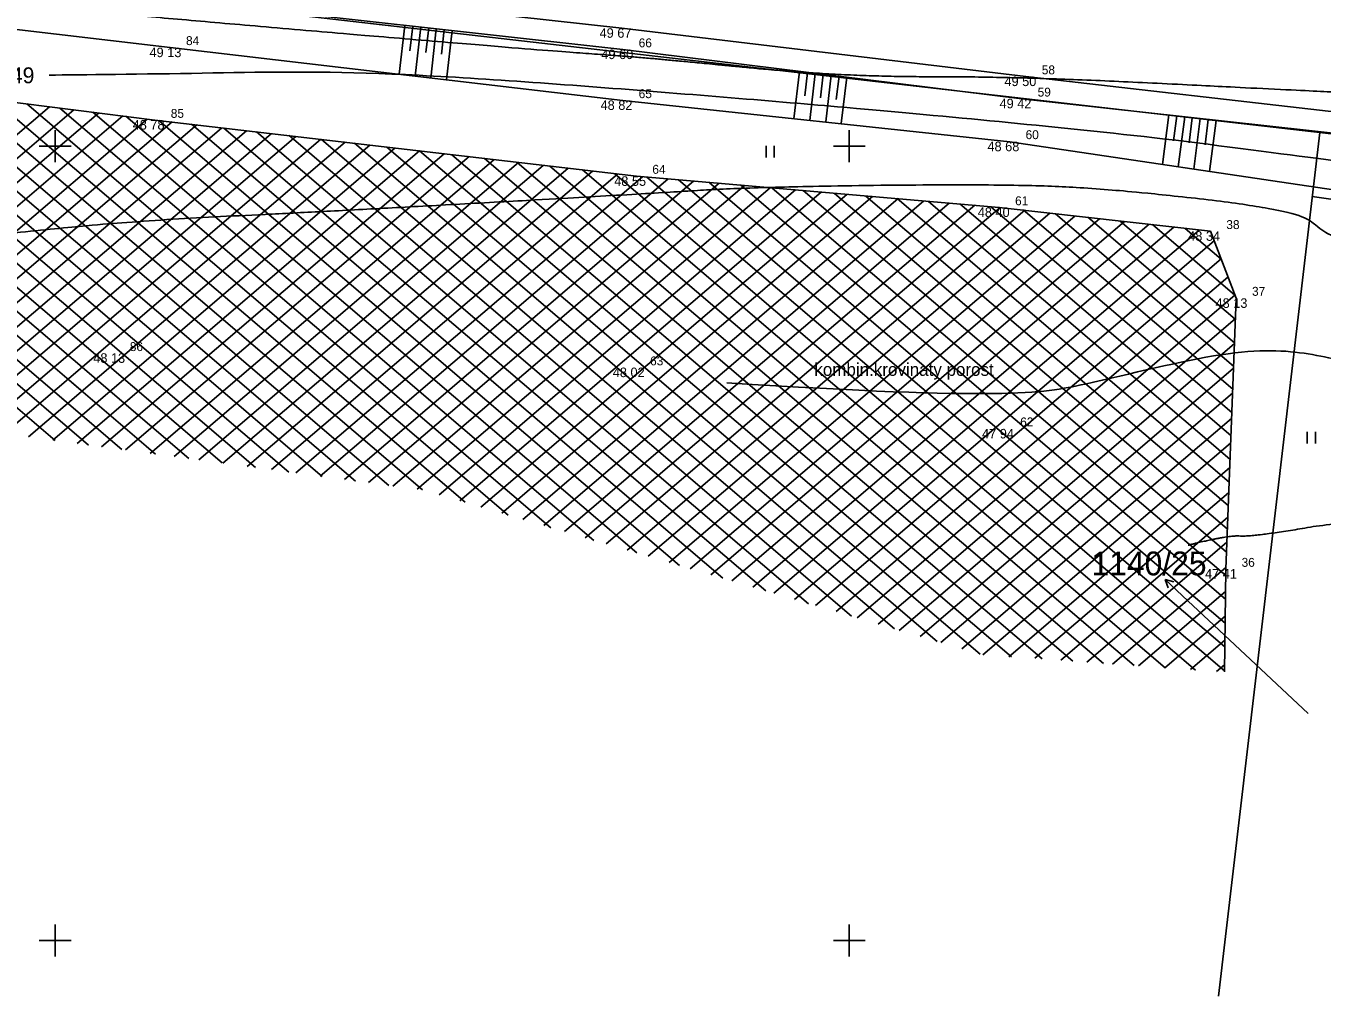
# Model space of a CAD drawing. Extents: x -704057 to -703795, y -1008732 to -1008584.
# Drawn here: x -703875.92 to -703835.12, y -1008701.75 to -1008671.22 of the extents above; entities that cross this region are included whole.
import ezdxf

# ---------------------------------------------------------------- set-up
doc = ezdxf.new("R2010")
doc.units = 0
for name, color, linetype in [('Z_body', 7, 'Continuous'), ('Z_body_cisla', 7, 'Continuous'), ('Z_body_vysky', 7, 'Continuous'), ('Z_hekt_sit', 7, 'Continuous'), ('Z_katastr_cisla_pozemkove', 7, 'Continuous'), ('Z_katastr_hranice', 7, 'Continuous'), ('Z_komunikace_zpevn_pl', 7, 'Continuous'), ('Z_popis', 7, 'Continuous'), ('Z_teren_hrany_paty', 7, 'Continuous'), ('Z_vrstevnice_popis', 7, 'Continuous'), ('Z_vrstevnice_vedlejsi', 7, 'Continuous'), ('Z_zelen_souvisla', 7, 'Continuous')]:
    doc.layers.add(name, color=color, linetype=linetype)

# ---------------------------------------------------------------- blocks, each defined once
blk = doc.blocks.new('POINT_DISPLAY')
blk.add_line((0, 0), (0, 0))
blk = doc.blocks.new('Z61')
for p, q in [((0, 0.75), (-0.13, 0.5)), ((0, 0), (0, 0.75)), ((0, 0.75), (0.13, 0.5))]:
    blk.add_line(p, q)
blk = doc.blocks.new('Z306')
for p, q in [((-0.13, 0.17), (-0.13, -0.2)), ((0.13, 0.17), (0.13, -0.2))]:
    blk.add_line(p, q)

msp = doc.modelspace()

# ---------------------------------------------------------------- linework, layer by layer
at = {"layer": 'Z_hekt_sit'}
for p, q in [((-703875, -1008674.5), (-703875, -1008675.5)), ((-703850, -1008674.5), (-703850, -1008675.5)), ((-703875.5, -1008675), (-703874.5, -1008675)), ((-703850.5, -1008675), (-703849.5, -1008675)), ((-703875, -1008699.5), (-703875, -1008700.5)), ((-703850, -1008699.5), (-703850, -1008700.5)), ((-703875.5, -1008700), (-703874.5, -1008700)), ((-703850.5, -1008700), (-703849.5, -1008700))]:
    msp.add_line(p, q, dxfattribs=at)
at = {"layer": 'Z_katastr_cisla_pozemkove'}
msp.add_lwpolyline([(-703835.55, -1008692.86), (-703839.51, -1008689.15)], dxfattribs=at)
at = {"layer": 'Z_katastr_hranice'}
for p, q in [((-703871.83, -1008670.35), (-703828.51, -1008675.34)), ((-703835.19, -1008674.57), (-703838.38, -1008701.75)), ((-703800.45, -1008681.63), (-703835.43, -1008676.59))]:
    msp.add_line(p, q, dxfattribs=at)
at = {"layer": 'Z_komunikace_zpevn_pl'}
for p, q in [((-703870.95, -1008669.76), (-703857.16, -1008671.29)), ((-703857.16, -1008671.29), (-703844.44, -1008672.81)), ((-703844.44, -1008672.81), (-703833.37, -1008674.08))]:
    msp.add_line(p, q, dxfattribs=at)
at = {"layer": 'Z_teren_hrany_paty'}
for p, q in [((-703883.41, -1008670.49), (-703871.38, -1008671.9)), ((-703857.13, -1008671.96), (-703871.14, -1008670.4)), ((-703863.99, -1008671.2), (-703864.17, -1008672.74)), ((-703863.74, -1008671.22), (-703863.83, -1008672)), ((-703863.49, -1008671.25), (-703863.67, -1008672.8)), ((-703863.24, -1008671.28), (-703863.33, -1008672.05)), ((-703863, -1008671.31), (-703863.17, -1008672.86)), ((-703862.75, -1008671.33), (-703862.84, -1008672.11)), ((-703862.5, -1008671.36), (-703862.68, -1008672.91)), ((-703871.38, -1008671.9), (-703857.13, -1008673.56)), ((-703844.57, -1008673.51), (-703857.13, -1008671.96)), ((-703851.57, -1008672.65), (-703851.74, -1008674.14)), ((-703851.32, -1008672.68), (-703851.4, -1008673.42)), ((-703851.07, -1008672.71), (-703851.24, -1008674.19)), ((-703850.82, -1008672.74), (-703850.91, -1008673.48)), ((-703850.57, -1008672.77), (-703850.74, -1008674.24)), ((-703850.32, -1008672.8), (-703850.41, -1008673.53)), ((-703850.08, -1008672.83), (-703850.25, -1008674.29)), ((-703857.13, -1008673.56), (-703844.95, -1008674.86)), ((-703834.19, -1008674.66), (-703844.57, -1008673.51)), ((-703839.94, -1008674.02), (-703840.14, -1008675.58)), ((-703839.69, -1008674.05), (-703839.79, -1008674.83)), ((-703839.44, -1008674.08), (-703839.65, -1008675.65)), ((-703839.2, -1008674.11), (-703839.3, -1008674.9)), ((-703838.95, -1008674.13), (-703839.15, -1008675.72)), ((-703838.7, -1008674.16), (-703838.8, -1008674.96)), ((-703838.45, -1008674.19), (-703838.66, -1008675.8)), ((-703844.95, -1008674.86), (-703833.82, -1008676.52))]:
    msp.add_line(p, q, dxfattribs=at)
at = {"layer": 'Z_vrstevnice_popis'}
for points in [[(-703875.185, -1008672.765), (-703874.223, -1008672.756), (-703870.137, -1008672.712), (-703865.404, -1008672.596), (-703857.13, -1008673.191), (-703849.187, -1008673.851), (-703844.786, -1008674.276), (-703839.886, -1008674.766), (-703834.01, -1008675.565), (-703833.183, -1008675.626), (-703829.469, -1008675.762), (-703820.395, -1008676.551), (-703819.724, -1008676.752), (-703817.382, -1008677.089), (-703816.139, -1008677.242), (-703815.655, -1008677.56), (-703814.182, -1008677.821), (-703814.089, -1008677.838)], [(-703853.857, -1008682.453), (-703845.141, -1008682.991), (-703842.815, -1008682.602), (-703837.88, -1008681.328), (-703835.453, -1008681.475), (-703833.605, -1008682.013), (-703832.889, -1008681.487), (-703832.436, -1008681.417), (-703832.363, -1008681.41)]]:
    msp.add_open_spline(points, degree=3, dxfattribs=at)
at = {"layer": 'Z_vrstevnice_vedlejsi'}
for points in [[(-703806.645, -1008669.413), (-703810.064, -1008669.091), (-703818.896, -1008668.231), (-703821.949, -1008667.886), (-703832.348, -1008666.911), (-703832.429, -1008666.905), (-703837.82, -1008666.255), (-703832.713, -1008666.908), (-703832.355, -1008666.952), (-703825.705, -1008667.99), (-703819.056, -1008669.026), (-703815.993, -1008669.415), (-703810.462, -1008670.24), (-703806.87, -1008671.09), (-703808.766, -1008673.591), (-703809.75, -1008673.886), (-703817.454, -1008673.52), (-703819.628, -1008673.248), (-703826.836, -1008673.24), (-703833.27, -1008673.353), (-703835.286, -1008673.278), (-703844.44, -1008672.81), (-703850.152, -1008672.821), (-703855.806, -1008672.275), (-703857.13, -1008672.165), (-703860.162, -1008671.947), (-703871.237, -1008671.005), (-703876.973, -1008670.473), (-703883.276, -1008669.953), (-703888.652, -1008669.207), (-703892.007, -1008668.787), (-703895.701, -1008668.459), (-703900.931, -1008667.965), (-703907.22, -1008668.487), (-703913.351, -1008668.979), (-703918.495, -1008669.549), (-703927.701, -1008668.863), (-703930.6, -1008669.724), (-703932.124, -1008670.909), (-703936.972, -1008673.376)], [(-703896.98, -1008678.651), (-703896.133, -1008678.493), (-703895.427, -1008678.464), (-703883.839, -1008678.545), (-703877.35, -1008677.837), (-703872.416, -1008677.342), (-703866.301, -1008677.05), (-703856.707, -1008676.518), (-703852.893, -1008676.277), (-703845.162, -1008676.191), (-703841.604, -1008676.353), (-703835.881, -1008677.017), (-703835.026, -1008677.731), (-703834.61, -1008677.894), (-703834.308, -1008677.982), (-703834.186, -1008677.892), (-703833.394, -1008677.301), (-703832.871, -1008677.385), (-703832.441, -1008677.368), (-703830.672, -1008676.925), (-703824.679, -1008677.145), (-703820.88, -1008677.475), (-703818.446, -1008678.206), (-703817.605, -1008678.327), (-703817.159, -1008678.382), (-703815.634, -1008679.383), (-703815.241, -1008679.772), (-703814.913, -1008679.988), (-703810.519, -1008681.242), (-703809.363, -1008681.548)], [(-703839.334, -1008687.561), (-703838.109, -1008687.245), (-703837.269, -1008687.296), (-703833.651, -1008686.681), (-703827.63, -1008686.764)]]:
    msp.add_open_spline(points, degree=2, dxfattribs=at)
at = {"layer": 'Z_zelen_souvisla'}
for p, q in [((-703889.57, -1008671.82), (-703875, -1008684.26)), ((-703888.5, -1008671.98), (-703873.95, -1008684.41)), ((-703887.43, -1008672.13), (-703872.9, -1008684.55)), ((-703886.36, -1008672.29), (-703871.84, -1008684.69)), ((-703885.3, -1008672.44), (-703870.79, -1008684.83)), ((-703884.23, -1008672.6), (-703869.74, -1008684.97)), ((-703883.16, -1008672.76), (-703868.69, -1008685.11)), ((-703871.86, -1008674.18), (-703883.14, -1008672.76)), ((-703882.12, -1008672.89), (-703867.64, -1008685.26)), ((-703881.08, -1008673.02), (-703866.59, -1008685.4)), ((-703880.04, -1008673.15), (-703865.54, -1008685.54)), ((-703879, -1008673.28), (-703864.49, -1008685.68)), ((-703877.97, -1008673.41), (-703863.44, -1008685.82)), ((-703885.78, -1008682.81), (-703875.18, -1008673.76)), ((-703885.01, -1008682.92), (-703874.41, -1008673.86)), ((-703876.93, -1008673.54), (-703862.09, -1008686.21)), ((-703875.89, -1008673.67), (-703860.74, -1008686.61)), ((-703874.85, -1008673.8), (-703859.39, -1008687.01)), ((-703884.25, -1008683.02), (-703873.64, -1008673.96)), ((-703883.48, -1008683.12), (-703872.87, -1008674.05)), ((-703882.72, -1008683.22), (-703872.1, -1008674.15)), ((-703881.95, -1008683.33), (-703871.32, -1008674.24)), ((-703873.81, -1008673.93), (-703858.04, -1008687.41)), ((-703872.77, -1008674.06), (-703856.69, -1008687.8)), ((-703856.7, -1008675.95), (-703871.86, -1008674.18)), ((-703871.74, -1008674.19), (-703855.34, -1008688.2)), ((-703881.19, -1008683.43), (-703870.54, -1008674.33)), ((-703880.43, -1008683.53), (-703869.76, -1008674.43)), ((-703879.66, -1008683.64), (-703868.98, -1008674.52)), ((-703878.9, -1008683.74), (-703868.2, -1008674.61)), ((-703870.71, -1008674.31), (-703853.98, -1008688.6)), ((-703869.69, -1008674.43), (-703852.63, -1008689)), ((-703868.66, -1008674.55), (-703851.28, -1008689.4)), ((-703867.63, -1008674.67), (-703849.93, -1008689.79)), ((-703878.13, -1008683.84), (-703867.42, -1008674.7)), ((-703877.37, -1008683.95), (-703866.65, -1008674.79)), ((-703876.6, -1008684.05), (-703865.87, -1008674.88)), ((-703875.84, -1008684.15), (-703865.09, -1008674.97)), ((-703875.07, -1008684.25), (-703864.31, -1008675.06)), ((-703866.61, -1008674.79), (-703848.58, -1008690.19)), ((-703865.58, -1008674.91), (-703847.23, -1008690.59)), ((-703864.56, -1008675.03), (-703845.88, -1008690.99)), ((-703874.31, -1008684.36), (-703863.53, -1008675.15)), ((-703873.54, -1008684.46), (-703862.75, -1008675.24)), ((-703872.78, -1008684.56), (-703861.97, -1008675.33)), ((-703872.01, -1008684.67), (-703861.19, -1008675.43)), ((-703863.53, -1008675.15), (-703844.89, -1008691.07)), ((-703862.51, -1008675.27), (-703843.93, -1008691.14)), ((-703861.48, -1008675.39), (-703842.96, -1008691.21)), ((-703860.46, -1008675.51), (-703842, -1008691.28)), ((-703871.25, -1008684.77), (-703860.41, -1008675.52)), ((-703870.48, -1008684.87), (-703859.64, -1008675.61)), ((-703869.72, -1008684.98), (-703858.86, -1008675.7)), ((-703868.95, -1008685.08), (-703858.08, -1008675.79)), ((-703868.19, -1008685.18), (-703857.3, -1008675.88)), ((-703859.43, -1008675.63), (-703841.03, -1008691.35)), ((-703858.4, -1008675.75), (-703840.06, -1008691.42)), ((-703857.38, -1008675.87), (-703839.1, -1008691.49)), ((-703867.42, -1008685.28), (-703856.51, -1008675.97)), ((-703866.66, -1008685.39), (-703855.71, -1008676.04)), ((-703865.89, -1008685.49), (-703854.9, -1008676.1)), ((-703865.13, -1008685.59), (-703854.1, -1008676.17)), ((-703864.37, -1008685.7), (-703853.3, -1008676.24)), ((-703863.6, -1008685.8), (-703852.49, -1008676.31)), ((-703845.28, -1008676.93), (-703856.7, -1008675.95)), ((-703856.37, -1008675.98), (-703838.19, -1008691.51)), ((-703855.38, -1008676.06), (-703838.18, -1008690.76)), ((-703854.4, -1008676.15), (-703838.17, -1008690.01)), ((-703853.41, -1008676.23), (-703838.16, -1008689.26)), ((-703852.43, -1008676.32), (-703838.15, -1008688.51)), ((-703862.91, -1008685.97), (-703851.69, -1008676.38)), ((-703862.26, -1008686.16), (-703850.88, -1008676.45)), ((-703861.6, -1008686.36), (-703850.08, -1008676.52)), ((-703860.94, -1008686.55), (-703849.27, -1008676.59)), ((-703860.28, -1008686.75), (-703848.47, -1008676.66)), ((-703859.62, -1008686.94), (-703847.66, -1008676.73)), ((-703851.45, -1008676.4), (-703838.13, -1008687.77)), ((-703850.46, -1008676.49), (-703838.1, -1008687.04)), ((-703849.48, -1008676.57), (-703838.07, -1008686.31)), ((-703848.49, -1008676.65), (-703838.04, -1008685.58)), ((-703858.96, -1008687.13), (-703846.86, -1008676.79)), ((-703858.31, -1008687.33), (-703846.05, -1008676.86)), ((-703857.65, -1008687.52), (-703845.25, -1008676.93)), ((-703856.99, -1008687.72), (-703844.47, -1008677.02)), ((-703856.33, -1008687.91), (-703843.69, -1008677.11)), ((-703847.51, -1008676.74), (-703838.02, -1008684.85)), ((-703846.52, -1008676.82), (-703837.99, -1008684.11)), ((-703845.54, -1008676.91), (-703837.96, -1008683.38)), ((-703838.63, -1008677.68), (-703845.28, -1008676.93)), ((-703844.53, -1008677.01), (-703837.93, -1008682.65)), ((-703843.51, -1008677.13), (-703837.9, -1008681.92)), ((-703855.67, -1008688.1), (-703842.9, -1008677.2)), ((-703855.01, -1008688.3), (-703842.12, -1008677.29)), ((-703854.36, -1008688.49), (-703841.34, -1008677.37)), ((-703853.7, -1008688.68), (-703840.56, -1008677.46)), ((-703853.04, -1008688.88), (-703839.78, -1008677.55)), ((-703842.49, -1008677.24), (-703837.87, -1008681.19)), ((-703841.47, -1008677.36), (-703837.85, -1008680.45)), ((-703840.45, -1008677.47), (-703837.86, -1008679.69)), ((-703852.38, -1008689.07), (-703838.99, -1008677.64)), ((-703839.43, -1008677.59), (-703838.29, -1008678.56)), ((-703837.82, -1008679.79), (-703838.63, -1008677.68)), ((-703851.72, -1008689.27), (-703838.51, -1008677.98)), ((-703851.06, -1008689.46), (-703838.29, -1008678.55)), ((-703850.41, -1008689.65), (-703838.08, -1008679.12)), ((-703849.75, -1008689.85), (-703837.86, -1008679.69)), ((-703838.15, -1008688.31), (-703837.82, -1008679.79)), ((-703849.09, -1008690.04), (-703837.85, -1008680.44)), ((-703848.43, -1008690.24), (-703837.88, -1008681.22)), ((-703847.77, -1008690.43), (-703837.91, -1008682)), ((-703847.12, -1008690.62), (-703837.94, -1008682.78)), ((-703846.46, -1008690.82), (-703837.97, -1008683.57)), ((-703845.79, -1008691.01), (-703838, -1008684.35)), ((-703844.98, -1008691.07), (-703838.03, -1008685.13)), ((-703844.16, -1008691.12), (-703838.06, -1008685.91)), ((-703843.34, -1008691.18), (-703838.09, -1008686.69)), ((-703842.52, -1008691.24), (-703838.12, -1008687.48)), ((-703841.71, -1008691.3), (-703838.15, -1008688.26)), ((-703838.19, -1008691.55), (-703838.15, -1008688.31)), ((-703840.89, -1008691.36), (-703838.16, -1008689.02)), ((-703840.07, -1008691.42), (-703838.17, -1008689.79)), ((-703839.26, -1008691.47), (-703838.18, -1008690.55)), ((-703838.44, -1008691.53), (-703838.19, -1008691.32))]:
    msp.add_line(p, q, dxfattribs=at)

# ---------------------------------------------------------------- block references
at = {"layer": 'Z_body'}
for p in [(-703857.16, -1008671.29), (-703871.38, -1008671.9), (-703857.13, -1008671.96), (-703844.44, -1008672.81), (-703857.13, -1008673.56), (-703844.57, -1008673.51), (-703871.86, -1008674.18), (-703844.95, -1008674.86), (-703856.7, -1008675.95), (-703845.28, -1008676.93), (-703838.63, -1008677.68), (-703837.82, -1008679.79), (-703873.15, -1008681.52), (-703856.77, -1008681.97), (-703845.12, -1008683.9), (-703838.15, -1008688.31)]:
    msp.add_blockref('POINT_DISPLAY', p, dxfattribs=at)
at = {"layer": 'Z_katastr_cisla_pozemkove', "rotation": 46.909200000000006}
msp.add_blockref('Z61', (-703839.51, -1008689.15), dxfattribs=at)
at = {"layer": 'Z_popis'}
for p in [(-703852.49, -1008675.16), (-703835.45, -1008684.16)]:
    msp.add_blockref('Z306', p, dxfattribs=at)

# ---------------------------------------------------------------- texts
at = {"layer": 'Z_body_cisla'}
for s, p in [('84', (-703870.88, -1008671.82)), ('66', (-703856.63, -1008671.89)), ('58', (-703843.94, -1008672.74)), ('65', (-703856.63, -1008673.49)), ('59', (-703844.07, -1008673.44)), ('85', (-703871.36, -1008674.11)), ('60', (-703844.45, -1008674.78)), ('64', (-703856.2, -1008675.87)), ('61', (-703844.78, -1008676.86)), ('38', (-703838.13, -1008677.61)), ('37', (-703837.32, -1008679.71)), ('86', (-703872.65, -1008681.45)), ('63', (-703856.27, -1008681.9)), ('62', (-703844.62, -1008683.82)), ('36', (-703837.65, -1008688.24))]:
    msp.add_text(s, height=0.28, dxfattribs=at).set_placement(p)
at = {"layer": 'Z_body_vysky'}
for s, p in [('49 67', (-703857.86, -1008671.59)), ('49 13', (-703872.03, -1008672.2)), ('49 60', (-703857.805, -1008672.26)), ('49 50', (-703845.115, -1008673.11)), ('48 82', (-703857.83, -1008673.86)), ('49 42', (-703845.27, -1008673.81)), ('48 78', (-703872.56, -1008674.48)), ('48 68', (-703845.65, -1008675.16)), ('48 55', (-703857.4, -1008676.25)), ('48 40', (-703845.955, -1008677.23)), ('48 34', (-703839.33, -1008677.98)), ('48 13', (-703838.47, -1008680.09)), ('48 13', (-703873.8, -1008681.82)), ('48 02', (-703857.445, -1008682.27)), ('47 94', (-703845.82, -1008684.2)), ('47 41', (-703838.8, -1008688.61))]:
    msp.add_text(s, height=0.3, dxfattribs=at).set_placement(p)
at = {"layer": 'Z_katastr_cisla_pozemkove'}
msp.add_text('1140/25', height=0.75, dxfattribs=at).set_placement((-703842.377, -1008688.51))
at = {"layer": 'Z_popis'}
msp.add_text('kombin.krovinaty porost', height=0.4, dxfattribs=at).set_placement((-703851.1, -1008682.23))
at = {"layer": 'Z_vrstevnice_popis'}
msp.add_text('249', height=0.5, rotation=0.5232, dxfattribs=at).set_placement((-703876.766, -1008673.03))

doc.saveas('drawing.dxf')
